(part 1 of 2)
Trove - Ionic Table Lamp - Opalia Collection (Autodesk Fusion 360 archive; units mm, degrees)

design "Marble Base - Ionic Table Lamp - Ketra Ready - 120V - Opalia Collection" references "Arca Tall", "Facet Petite", "Ketra - A20 Tunable Lamp", "Marble Base - Ionic Table Lamp - Ketra Ready - 120V", "Trove - TL", "Chinois", "Arca Petite"
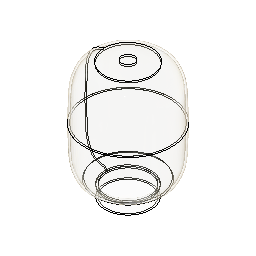
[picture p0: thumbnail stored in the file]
component_insert "Component Insert2"
component_insert "Component Insert3"
component_insert "Component Insert4"
component_insert "Component Insert5"
position "Position1"
component_insert "Component Insert6"
component_insert "Component Insert7"
component_insert "Component Insert8"

design "Arca Petite"
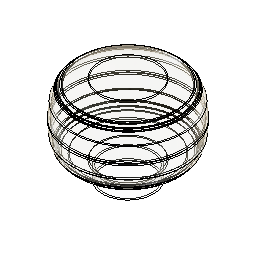
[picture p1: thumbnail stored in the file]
sketch "Sketch1" plane through (0, 0, 0) normal (0, 1, 0) x axis (1, 0, 0)
  line L1 (0, 101.6) -> (0, -101.6)
  line L2 (127, 0) -> (-127, 0)
  line L3 (63.5, 101.6) -> (-63.5, 101.6)
  perpendicular L1 L2
  parallel L2 L3
sketch "Sketch2" plane through (0, 0, 0) normal (0, 1, 0) x axis (1, 0, 0)
  line L1 (0, 101.6) -> (0, -101.6)
  line L2 (0, -76.2) -> (0, 101.6)
  line L3 (127, 0) -> (-127, 0)
  line L4 (114.3, 0) -> (-114.3, 0)
  line L5 (50.8, 101.6) -> (50.8, 63.5)
  line L6 (-50.8, 101.6) -> (50.8, 101.6)
  line L7 (-50.8, 63.5) -> (-50.8, 101.6)
  line L8 (63.5, 101.6) -> (-63.5, 101.6)
  line L9 (114.3, -76.2) -> (114.3, 63.5)
  line L10 (-114.3, -76.2) -> (114.3, -76.2)
  line L11 (-114.3, 63.5) -> (-114.3, -76.2)
  line L12 (-50.8, 63.5) -> (-114.3, 63.5)
  line L13 (114.3, 63.5) -> (50.8, 63.5)
  point P2 (0, 101.6)
  point P5 (0, 101.6)
  point P6 (0, -76.2)
  point P9 (-114.3, 0)
  point P10 (114.3, 0)
  point P11 (50.8, 101.6)
  point P19 (50.8, 63.5)
  coincident P2 P5
  coincident L1 P6
  coincident L3 P9
  coincident L3 P10
  vertical L5
  horizontal L6
  vertical L7
  coincident P11 L8
  horizontal L12
  vertical L9
  horizontal L10
  vertical L11
  coincident P19 L12
  collinear L12 L13
derived_base_feature "Derived Base Feature"
revolve "Revolve1" sketch "Sketch4" AlongAngle 360 bodies "Arca Petite"
shell "Shell1" innerThickness 3.81
component_from_bodies "Body->Comp"
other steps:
base_feature "Base Feature" bodies "Arca Petite"
create_component "CreateComponent1"
remove_body "RemoveBody1"
named bodies: "Arca Petite"

design "Neoprene Pad"
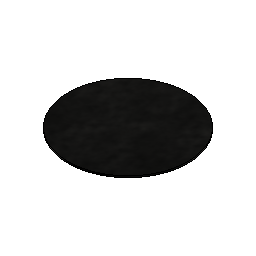
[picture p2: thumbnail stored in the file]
sketch "Sketch1" plane through (0, 0, 0) normal (0, 0, 1) x axis (1, 0, 0)
  circle C1 centre (0, 0) radius 57.15
  point P1 (0, 0)
  point P2 (0, 0)
  coincident P1 P2
extrude "Extrude1" new body sketch "Sketch1" along normal blind 1.5875 bodies "Neoprene Pad"
component_from_bodies "Body->Comp"
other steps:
base_feature "Base Feature" bodies "Neoprene Pad"
create_component "CreateComponent1"
remove_body "RemoveBody1"
named bodies: "Neoprene Pad"

design "T9 - Bulb"
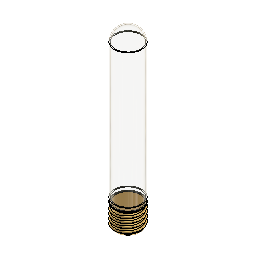
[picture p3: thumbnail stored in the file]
sketch "Sketch1" plane through (0, 0, 0) normal (0, 1, 0) x axis (1, 0, 0)
  line L1 (0, -166.37) -> (0, 0)
  line L2 (13.97, -13.97) -> (13.97, -152.4)
  line L3 (-13.97, -152.4) -> (-13.97, -13.97)
  line L4 (0, 0) -> (0, -166.37)
  line L5 (12.97, -13.97) -> (12.97, -152.4)
  line L6 (-12.97, -152.4) -> (-12.97, -13.97)
  line L7 (-12.3978, -10.16) -> (-13.4404, -10.16)
  line L8 (13.4404, -10.16) -> (12.3978, -10.16)
  arc A1 centre (0, -152.4) radius 13.97 clockwise from (13.97, -152.4) to (-13.97, -152.4)
  arc A2 centre (0, -152.4) radius 12.97 clockwise from (12.97, -152.4) to (-12.97, -152.4)
  arc A3 centre (0, -13.97) radius 13.97 clockwise from (13.4404, -10.16) to (13.97, -13.97)
  arc A4 centre (0, -13.97) radius 13.97 clockwise from (-13.97, -13.97) to (-13.4404, -10.16)
  arc A5 centre (0, -13.97) radius 12.97 clockwise from (12.3978, -10.16) to (12.97, -13.97)
  arc A6 centre (0, -13.97) radius 12.97 clockwise from (-12.97, -13.97) to (-12.3978, -10.16)
  point P1 (0, 0)
  point P2 (0, 0)
  point P3 (0, -166.37)
  point P10 (0, 0)
  point P17 (13.4404, -10.16)
  point P19 (12.3978, -10.16)
  point P4 (13.97, -152.4)
  point P5 (13.97, -13.97)
  coincident P1 P2
  vertical L1
  tangent L2 A3
  tangent L3 A3
  parallel L2 L3
  tangent L3 A1
  tangent L2 A1
  midpoint P3 A1
  coincident P1 P10
  perpendicular L1 L7
  coincident P17 L7
  concentric A3 A4
  coincident P10 A3
  concentric A1 A2
  tangent L5 A2
  tangent L5 A5
  tangent L6 A5
  tangent L6 A2
  coincident P19 L7
  concentric A5 A6
  collinear L7 L8
  dimension "d6" distance L2 L3 = 27.94
  dimension "d7" distance P4 P5 = 138.43
revolve "Revolve1" sketch "Sketch1" AlongAngle 360 bodies "T9"
derived_base_feature "Derived Base Feature" bodies "E26 Base"
align "Align1"
move "Move1"
component_from_bodies "Body->Comp1"
component_from_bodies "Body->Comp2"
copy_paste "CutPaste1"
copy_paste "CutPaste2"
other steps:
base_feature "Base Feature1" bodies "T9"
base_feature "Base Feature1" bodies "E26 Base"
create_component "CreateComponent1"
create_component "CreateComponent2"
remove_body "RemoveBody1"
create_component "CreateComponent3"
remove_body "RemoveBody2"
remove_instance "RemoveInstance1"
remove_instance "RemoveInstance2"
named bodies: "T9", "E26 Base"

design "Marble Base - Silicone Gasket"
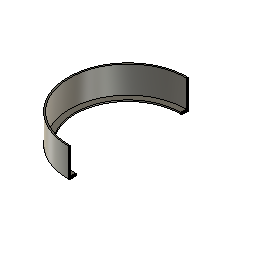
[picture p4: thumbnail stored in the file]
sketch "Sketch1" plane through (0, 0, 0) normal (0, 0, 1) x axis (1, 0, 0)
  circle C1 centre (0, 0) radius 53.34
  point P1 (0, 0)
  point P2 (0, 0)
  coincident P1 P2
extrude "Extrude1" new body sketch "Sketch1" along normal blind 25.4 bodies "Silicone Gasket"
shell "Shell1" innerThickness 1.27
sketch "Sketch2" plane through (0, 0, 1.27) normal (0, 0, 1) x axis (-1, 0, 0)
  circle C1 centre (0, 0) radius 52.07
  circle C2 centre (0, 0) radius 46.99
  concentric C1 C2
extrude "Extrude2" cut sketch "Sketch2" profile of C2 against normal blind 12.7
component_from_bodies "Body->Comp"
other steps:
base_feature "Base Feature" bodies "Silicone Gasket"
create_component "CreateComponent1"
remove_body "RemoveBody1"
named bodies: "Silicone Gasket"

design "2-Pole Plug End"
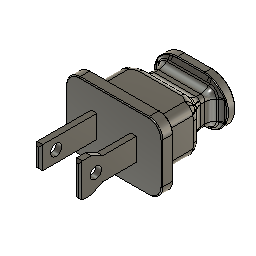
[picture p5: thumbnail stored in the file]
sketch "Sketch1" plane through (0, 0, 0) normal (0, 1, 0) x axis (1, 0, 0)
  line L1 (9.6837, 9.525) -> (-9.6837, 9.525)
  line L2 (13.4938, -5.715) -> (13.4938, 5.715)
  line L3 (-9.6837, -9.525) -> (9.6837, -9.525)
  line L4 (-13.4937, 5.715) -> (-13.4937, -5.715)
  line L5 (13.4938, -9.525) -> (-13.4937, 9.525)
  line L6 (-13.4937, -9.525) -> (13.4938, 9.525)
  arc A1 centre (-9.6837, -5.715) radius 3.81 clockwise from (-9.6837, -9.525) to (-13.4937, -5.715)
  arc A2 centre (9.6837, -5.715) radius 3.81 clockwise from (13.4938, -5.715) to (9.6837, -9.525)
  arc A3 centre (9.6837, 5.715) radius 3.81 clockwise from (9.6837, 9.525) to (13.4938, 5.715)
  arc A4 centre (-9.6837, 5.715) radius 3.81 clockwise from (-13.4937, 5.715) to (-9.6837, 9.525)
  point P6 (0, 0)
  point P1 (0, 0)
  point P5 (-13.4937, -9.525)
  point P4 (13.4938, -9.525)
  point P3 (13.4938, 9.525)
  point P2 (-13.4937, 9.525)
  horizontal L1
  perpendicular L1 L2
  parallel L1 L3
  parallel L2 L4
  coincident L5 P6
  coincident L6 P6
  coincident P1 P6
  coincident P5 L4
  coincident P5 L3
  tangent L4 A1
  tangent L3 A1
  coincident P4 L3
  coincident P4 L2
  tangent L3 A2
  tangent L2 A2
  equal A1 A2
  coincident P3 L2
  coincident P3 L1
  tangent L2 A3
  tangent L1 A3
  equal A1 A3
  coincident P2 L1
  coincident P2 L4
  tangent L1 A4
  tangent L4 A4
  equal A1 A4
  dimension "d1" distance P4 P5 = 26.9875
  dimension "d2" distance P2 P5 = 19.05
  dimension "d3" radius A1 = 3.81
extrude "Extrude1" new body sketch "Sketch1" profile of L1 L2 L3 L4 A1 A2 A3 A4 along normal blind 3.175
sketch "Sketch2" plane through (0, 3.175, 0) normal (0, 1, 0) x axis (-1, 0, 0)
  line L1 (9.6837, -9.525) -> (-9.6837, -9.525)
  line L2 (13.4937, 5.715) -> (13.4937, -5.715)
  line L3 (-9.6837, 9.525) -> (9.6837, 9.525)
  line L4 (-13.4938, -5.715) -> (-13.4938, 5.715)
  line L5 (10.16, -6.35) -> (-10.16, -6.35)
  line L6 (10.16, 6.35) -> (10.16, -6.35)
  line L7 (-10.16, 6.35) -> (10.16, 6.35)
  line L8 (-10.16, -6.35) -> (-10.16, 6.35)
  line L9 (10.16, 6.35) -> (-10.16, -6.35)
  line L10 (-10.16, 6.35) -> (10.16, -6.35)
  arc A1 centre (-9.6837, -5.715) radius 3.81 clockwise from (-9.6837, -9.525) to (-13.4938, -5.715)
  arc A2 centre (9.6837, -5.715) radius 3.81 clockwise from (13.4937, -5.715) to (9.6837, -9.525)
  arc A3 centre (9.6837, 5.715) radius 3.81 clockwise from (9.6837, 9.525) to (13.4937, 5.715)
  arc A4 centre (-9.6837, 5.715) radius 3.81 clockwise from (-13.4938, 5.715) to (-9.6837, 9.525)
  point P18 (0, 0)
  point P1 (0, 0)
  horizontal L5
  perpendicular L5 L6
  parallel L5 L7
  parallel L6 L8
  coincident L9 P18
  coincident L10 P18
  coincident P1 P18
extrude "Extrude2" add sketch "Sketch2" profile of L5 L6 L7 L8 along normal blind 9.525
sketch "Sketch3" plane through (0, 12.7, 0) normal (0, 1, 0) x axis (-1, 0, 0)
  line L1 (-10.16, -6.35) -> (-10.16, 6.35)
  line L2 (10.16, -6.35) -> (-10.16, -6.35)
  line L3 (10.16, 6.35) -> (10.16, -6.35)
  line L4 (-10.16, 6.35) -> (10.16, 6.35)
  line L5 (-7.1437, 3.9688) -> (7.1437, 3.9688)
  line L6 (-7.1437, -3.9688) -> (-7.1437, 3.9688)
  line L7 (7.1437, -3.9688) -> (-7.1437, -3.9688)
  line L8 (7.1437, 3.9688) -> (7.1437, -3.9688)
  line L9 (-7.1437, -3.9688) -> (7.1437, 3.9688)
  line L10 (7.1437, -3.9688) -> (-7.1437, 3.9688)
  point P10 (0, 0)
  point P1 (0, 0)
  point P8 (-7.1437, -3.9688)
  point P9 (7.1437, -3.9688)
  point P7 (-7.1437, 3.9688)
  horizontal L5
  perpendicular L5 L6
  parallel L5 L7
  parallel L6 L8
  coincident L9 P10
  coincident L10 P10
  coincident P1 P10
  dimension "d8" distance P8 P9 = 14.2875
  dimension "d9" distance P7 P8 = 7.9375
extrude "Extrude3" add sketch "Sketch3" profile of L5 L6 L7 L8 along normal blind 11.1125
fillet "Fillet1" radius 2.286 1.27 0.254
chamfer "Chamfer1" distance 3.429
fillet "Fillet2" radius 2.54 1.905
sketch "Sketch4" plane through (0, 23.8125, 0) normal (0, 1, 0) x axis (-1, 0, 0)
  line L1 (-7.1437, -2.6987) -> (-7.1437, 2.6987)
  line L2 (5.8737, -3.9688) -> (-5.8737, -3.9688)
  line L3 (7.1437, 2.6987) -> (7.1437, -2.6987)
  line L4 (-5.8737, 3.9688) -> (5.8737, 3.9688)
  line L5 (-3.81, 6.604) -> (3.81, 6.604)
  line L6 (3.81, -6.604) -> (-3.81, -6.604)
  line L7 (-10.414, 0) -> (10.414, 0)
  arc A1 centre (-5.8737, 2.6987) radius 1.27 clockwise from (-7.1437, 2.6987) to (-5.8737, 3.9688)
  arc A2 centre (-5.8737, -2.6987) radius 1.27 clockwise from (-5.8737, -3.9688) to (-7.1437, -2.6987)
  arc A3 centre (5.8737, -2.6987) radius 1.27 clockwise from (7.1437, -2.6987) to (5.8737, -3.9688)
  arc A4 centre (5.8737, 2.6987) radius 1.27 clockwise from (5.8737, 3.9688) to (7.1437, 2.6987)
  arc A5 centre (-3.81, 0) radius 6.604 clockwise from (-3.81, -6.604) to (-3.81, 6.604)
  arc A6 centre (3.81, 0) radius 6.604 clockwise from (3.81, 6.604) to (3.81, -6.604)
  point P20 (10.414, 0)
  point P21 (-10.414, 0)
  tangent L5 A5
  tangent A5 L6
  parallel L5 L6
  tangent L6 A6
  tangent L5 A6
  midpoint A6 P20
  midpoint A5 P21
  perpendicular L1 L7
extrude "Extrude4" add sketch "Sketch4" profile of A1 L1 A2 L2 A3 L3 A4 L4 L5 A5 L6 A6 against normal blind 2.286
chamfer "Chamfer2" distance 1.778
fillet "Fillet3" radius 1.778
fillet "Fillet4" radius 0.254
fillet "Fillet5" radius 0.254
fillet "Fillet6" radius 0.254
fillet "Fillet7" radius 3.175
sketch "Sketch5" plane through (0, 0, 0) normal (0, -1, 0) x axis (1, 0, 0)
  line L1 (-13.2397, -5.715) -> (-13.2397, 5.715)
  line L2 (9.6837, -9.271) -> (-9.6837, -9.271)
  line L3 (13.2397, 5.715) -> (13.2397, -5.715)
  line L4 (-9.6837, 9.271) -> (9.6837, 9.271)
  line L5 (-6.35, -3.175) -> (-6.35, 3.175)
  line L6 (6.35, 3.175) -> (-6.35, -3.175)
  line L7 (-6.35, 3.175) -> (6.35, -3.175)
  line L8 (-4.7625, 3.175) -> (-6.35, 3.175)
  line L9 (-4.7625, -3.175) -> (-4.7625, 3.175)
  line L10 (-6.35, -3.175) -> (-4.7625, -3.175)
  line L11 (-6.35, 3.175) -> (-6.35, -3.175)
  line L12 (0, -3.302) -> (0, 3.81)
  line L13 (4.7625, -3.175) -> (4.7625, 3.175)
  line L14 (4.7625, 3.175) -> (6.35, 3.175)
  line L15 (6.35, -3.175) -> (6.35, 3.175)
  line L16 (6.35, -3.175) -> (4.7625, -3.175)
  arc A1 centre (-9.6837, 5.715) radius 3.556 clockwise from (-13.2397, 5.715) to (-9.6837, 9.271)
  arc A2 centre (-9.6837, -5.715) radius 3.556 clockwise from (-9.6837, -9.271) to (-13.2397, -5.715)
  arc A3 centre (9.6837, -5.715) radius 3.556 clockwise from (13.2397, -5.715) to (9.6837, -9.271)
  arc A4 centre (9.6837, 5.715) radius 3.556 clockwise from (9.6837, 9.271) to (13.2397, 5.715)
  point P18 (0, 0)
  point P1 (0, 0)
  point P14 (-6.35, -3.175)
  point P27 (6.35, -3.175)
  point P17 (-6.35, 3.175)
  point P26 (6.35, 3.175)
  point P19 (-4.7625, 3.175)
  point P24 (4.7625, 3.175)
  point P20 (-4.7625, -3.175)
  point P25 (4.7625, -3.175)
  point P21 (-6.35, -3.175)
  point P28 (6.35, -3.175)
  point P15 (6.35, -3.175)
  point P16 (6.35, 3.175)
  coincident L6 P18
  coincident L7 P18
  coincident P1 P18
  horizontal L8
  vertical L9
  horizontal L10
  vertical L11
  vertical L12
  symmetric P14 L12 P27
  symmetric P17 L12 P26
  symmetric P19 L12 P24
  symmetric P20 L12 P25
  symmetric P21 L12 P28
  dimension "d36" distance P15 P16 = 6.35
  dimension "d37" distance P17 P19 = 1.5875
extrude "Extrude5" add sketch "Sketch5" profile of L5 L8 L9 L10 L11 L13 L14 L15 L16 along normal blind 15.875
sketch "Sketch7" plane through (0, 0, 3.175) normal (0, 0, 1) x axis (-1, 0, 0)
  line L1 (-4.7625, 0) -> (-6.35, 0)
  line L2 (-4.7625, 15.875) -> (-4.7625, 0)
  line L3 (-6.35, 15.875) -> (-4.7625, 15.875)
  line L4 (-6.35, 0) -> (-6.35, 15.875)
  line L5 (-4.7625, 15.875) -> (-6.35, 15.875)
  line L6 (-4.7625, 9.525) -> (-4.7625, 15.875)
  line L7 (-6.35, 9.525) -> (-4.7625, 9.525)
  line L8 (-6.35, 15.875) -> (-6.35, 9.525)
  point P5 (-6.35, 15.875)
  point P6 (-6.35, 15.875)
  point P9 (-6.35, 9.525)
  horizontal L5
  vertical L6
  horizontal L7
  vertical L8
  coincident P5 P6
  dimension "d45" distance P6 P9 = 6.35
extrude "Extrude7" add sketch "Sketch7" profile of L2 L3 L4 L5 L6 L7 L8 against normal blind 7.9375 and along normal blind 1.5875
chamfer "Chamfer3" distance 0.508
chamfer "Chamfer4" distance 0.635 distance 0.635
sketch "Sketch6" plane through (6.35, 0, 0) normal (1, 0, 0) x axis (0, 1, 0)
  line L1 (0, -3.175) -> (-9.525, -3.175)
  line L2 (0, 3.175) -> (0, -3.175)
  line L3 (-9.525, 3.175) -> (0, 3.175)
  line L4 (-15.367, -4.6355) -> (-15.367, 4.6355)
  line L5 (-11.43, 0) -> (-16.002, 0)
  line L6 (-9.525, -4.7625) -> (-15.24, -4.7625)
  line L7 (-9.525, -3.175) -> (-9.525, -4.7625)
  line L8 (-9.525, 4.7625) -> (-9.525, 3.175)
  line L9 (-15.24, 4.7625) -> (-9.525, 4.7625)
  line L10 (-15.24, -4.7625) -> (-15.367, -4.6355)
  line L11 (-15.367, 4.6355) -> (-15.24, 4.7625)
  circle C1 centre (-11.43, 0) radius 1.5875
  point P9 (-11.43, 0)
  point P10 (-11.43, 0)
  perpendicular L4 L5
  coincident P9 P10
  dimension "d42" diameter C1 = 3.175
extrude "Extrude6" cut sketch "Sketch6" profile of C1 against normal blind 20.32
chamfer "Chamfer5" distance 3.175 distance 1.5875 distance 3.175 distance 1.5875
component_from_bodies "Body->Comp"
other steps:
base_feature "Base Feature" bodies "2-Pole Plug End"
create_component "CreateComponent1"
remove_body "RemoveBody1"
named bodies: "2-Pole Plug End"

design "Facet Petite"
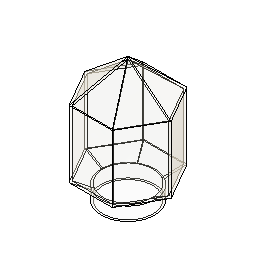
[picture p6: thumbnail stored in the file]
sketch "Sketch7" plane through (0, 0, 0) normal (1, 0, 0) x axis (0, 1, 0)
sketch "Sketch8" plane through (0, 0, 0) normal (0, 0, 1) x axis (1, 0, 0)
  circle C1 centre (0, 0) radius 50.8
  point P1 (0, 0)
  point P2 (0, 0)
  coincident P1 P2
  dimension "d17" diameter C1 = 101.6
extrude "Extrude5" new body sketch "Sketch8" along normal blind 25.4 and against normal blind 25.4
work_plane "WorkPlane1" AlongDistance 17.78
sketch "Sketch10" plane through (0, 0, 25.4) normal (0, 0, 1) x axis (-1, 0, 0)
  circle C1 centre (0, 0) radius 50.8
sketch "Sketch12" plane through (0, 0, 43.18) normal (0, 0, 1) x axis (1, 0, 0)
  line L1 (-82.1223, 0) -> (-41.0612, 71.12)
  line L2 (-41.0612, -71.12) -> (-82.1223, 0)
  line L3 (41.0612, -71.12) -> (-41.0612, -71.12)
  line L4 (82.1223, 0) -> (41.0612, -71.12)
  line L5 (41.0612, 71.12) -> (82.1223, 0)
  line L6 (-41.0612, 71.12) -> (41.0612, 71.12)
  point P1 (0, 0)
  point P8 (0, 0)
  coincident P1 P8
  dimension "d22" distance P8 L6 = 71.12
sketch "Sketch15" plane through (0, 0, 0) normal (0, 1, 0) x axis (1, 0, 0)
  line L1 (53.7365, -21.6801) -> (82.1223, -43.18)
  line L2 (-50.8, -25.4) -> (-82.1223, -43.18)
  point P2 (82.1223, -43.18)
  point P3 (82.1223, -43.18)
  point P5 (-82.1223, -43.18)
  point P7 (-82.1223, -43.18)
  point P6 (-50.8, -25.4)
  point P8 (-50.8, -25.4)
  coincident P2 P3
  coincident P5 P7
  coincident P6 P8
sketch "Sketch17" plane through (0, 0, 25.4) normal (0, 0, 1) x axis (-1, 0, 0)
  line L1 (51.3255, 0) -> (0, 0)
  line L2 (73.3235, 0) -> (0, 0)
  line L3 (-41.0612, -71.12) -> (-25.4, -43.9941)
  line L4 (-36.6617, -63.5) -> (-25.4, -43.9941)
  line L5 (78.4305, 0) -> (0, 0)
  line L6 (41.0612, -71.12) -> (25.4, -43.9941)
  line L7 (25.4, 43.9941) -> (41.0612, 71.12)
  line L8 (73.3235, 0) -> (0, 0)
  line L9 (-25.4, 43.9941) -> (-41.0612, 71.12)
  line L10 (0, 0) -> (0, 0)
  circle C1 centre (0, 0) radius 50.8
  point P1 (0, 0)
  point P4 (0, 0)
  point P2 (-41.0612, -71.12)
  point P6 (-41.0612, -71.12)
  point P3 (0, 0)
  point P7 (0, 0)
  point P9 (-25.4, -43.9941)
  point P12 (41.0612, -71.12)
  point P13 (41.0612, -71.12)
  point P15 (25.4, -43.9941)
  point P16 (41.0612, 71.12)
  point P17 (41.0612, 71.12)
  point P18 (25.4, 43.9941)
  point P19 (-41.0612, 71.12)
  point P20 (-41.0612, 71.12)
  point P21 (0, 0)
  point P23 (-25.4, 43.9941)
  point P25 (0, 0)
  point P24 (0, 0)
  point P26 (0, 0)
  horizontal L1
  coincident P1 P4
  coincident P2 P6
  horizontal L2
  coincident P3 P7
  coincident C1 P9
  coincident P12 P13
  horizontal L5
  coincident C1 P15
  coincident P16 P17
  coincident C1 P18
  coincident P19 P20
  horizontal L8
  coincident P1 P21
  coincident C1 P23
  coincident P1 P25
  coincident P24 P26
extrude "Extrude6" new body sketch "Sketch12" along normal blind 127
work_plane "WorkPlane2" AlongDistance 66.04
sketch "Sketch18" plane through (0, 0, 236.22) normal (0, 0, 1) x axis (1, 0, 0)
  line L1 (41.0612, -71.12) -> (0, 0)
  line L2 (82.1223, 0) -> (0, 0)
  line L3 (41.0612, 71.12) -> (0, 0)
  line L4 (-41.0612, 71.12) -> (0, 0)
  line L5 (-82.1223, 0) -> (0, 0)
  line L6 (-41.0612, -71.12) -> (0, 0)
  point P1 (0, 0)
  point P3 (0, 0)
  point P2 (41.0612, -71.12)
  point P4 (41.0612, -71.12)
  point P6 (0, 0)
  point P5 (82.1223, 0)
  point P7 (82.1223, 0)
  point P9 (0, 0)
  point P8 (41.0612, 71.12)
  point P10 (41.0612, 71.12)
  point P12 (0, 0)
  point P11 (-41.0612, 71.12)
  point P13 (-41.0612, 71.12)
  point P15 (0, 0)
  point P14 (-82.1223, 0)
  point P16 (-82.1223, 0)
  point P18 (0, 0)
  point P17 (-41.0612, -71.12)
  point P19 (-41.0612, -71.12)
  coincident P1 P3
  coincident P2 P4
  coincident P1 P6
  coincident P5 P7
  coincident P1 P9
  coincident P8 P10
  coincident P1 P12
  coincident P11 P13
  coincident P1 P15
  coincident P14 P16
  coincident P1 P18
  coincident P17 P19
loft "Loft1"
loft "Loft2" sketch "Sketch17"
component_from_bodies "Body->Comp"
extrude "Extrude1" cut of existing geometry blind -25.4
shell "Shell2" innerThickness 3.81
fillet "Fillet1" radius 7.62
fillet "Fillet2" radius 6.35
fillet "Fillet3" radius 6.35
fillet "Fillet4" radius 6.35
fillet "Fillet5" radius 6.35
fillet "Fillet6" radius 6.35
fillet "Fillet7" radius 3.81
fillet "Fillet8" radius 6.35
fillet "Fillet9" radius 6.35
fillet "Fillet10" radius 6.35
fillet "Fillet11" radius 6.35
fillet "Fillet12" radius 6.35
fillet "Fillet13" radius 2.286
shell "Shell1" innerThickness 2.54
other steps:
base_feature "Base Feature"
create_component "CreateComponent3"
remove_body "RemoveBody2"

design "Chinois"
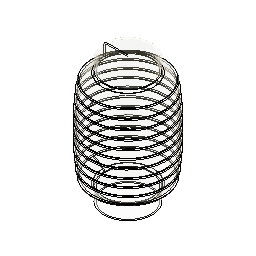
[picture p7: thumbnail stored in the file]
named bodies: "Chinois"

design "Marble Base - Plastic Insert"
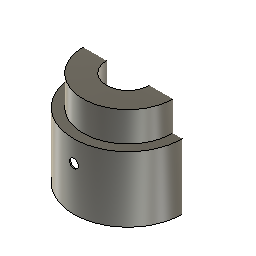
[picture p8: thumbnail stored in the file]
sketch "Sketch1" plane through (0, 0, 0) normal (0, 0, 1) x axis (1, 0, 0)
  circle C1 centre (0, 0) radius 50.038
  point P1 (0, 0)
  point P2 (0, 0)
  coincident P1 P2
  dimension "d1" diameter C1 = 100.076
extrude "Extrude1" new body sketch "Sketch1" along normal blind 72.898 bodies "Plastic Insert"
shell "Shell1" innerThickness 1.016
work_plane "WorkPlane1" AlongDistance 18.034
sketch "Sketch2" plane through (0, 0, 90.932) normal (0, 0, 1) x axis (1, 0, 0)
  circle C1 centre (0, 0) radius 20.701
  point P1 (0, 0)
  point P2 (0, 0)
  coincident P1 P2
  dimension "d6" diameter C1 = 41.402
extrude "Extrude2" add sketch "Sketch2" against normal blind 65.024
shell "Shell2" innerThickness 1.016
sketch "Sketch3" plane through (0, 0, 0) normal (0, 1, 0) x axis (1, 0, 0)
  line L1 (5.08, -20.32) -> (-5.08, -20.32)
  line L2 (5.08, 20.32) -> (5.08, -20.32)
  line L3 (-5.08, 20.32) -> (5.08, 20.32)
  line L4 (-5.08, -20.32) -> (-5.08, 20.32)
  line L5 (5.08, 20.32) -> (-5.08, -20.32)
  line L6 (-5.08, 20.32) -> (5.08, -20.32)
  point P6 (0, 0)
  point P1 (0, 0)
  horizontal L1
  perpendicular L1 L2
  parallel L1 L3
  parallel L2 L4
  coincident L5 P6
  coincident L6 P6
  coincident P1 P6
extrude "Extrude3" cut sketch "Sketch3" profile of L1 L2 L3 L4 along normal blind 91.44
sketch "Sketch4" plane through (0, 0, 0) normal (0, 1, 0) x axis (1, 0, 0)
  line L1 (0, -40.64) -> (0, 0)
  circle C1 centre (0, -40.64) radius 4.064
  point P1 (0, 0)
  point P2 (0, 0)
  point P3 (0, -40.64)
  point P4 (0, -40.64)
  coincident P1 P2
  vertical L1
  coincident P3 P4
  dimension "d12" diameter C1 = 8.128
work_plane "WorkPlane2" AlongDistance -91.44
sketch "Sketch5" plane through (0, -91.44, 0) normal (0, 1, 0) x axis (1, 0, 0)
  circle C1 centre (0, -40.64) radius 4.064
extrude "Extrude4" cut sketch "Sketch5" along normal blind 63.5
sketch "Sketch6" plane through (0, 0, 26.924) normal (0, 0, 1) x axis (-1, 0, 0)
  circle C1 centre (0, 0) radius 19.685
  circle C2 centre (0, 0) radius 5.461
  concentric C1 C2
  dimension "d16" diameter C2 = 10.922
extrude "Extrude5" cut sketch "Sketch6" profile of C2 against normal blind 15.24
sketch "Sketch7" plane through (0, 0, 72.898) normal (0, 0, 1) x axis (-1, 0, 0)
  circle C1 centre (0, 0) radius 20.701
  circle C2 centre (0, 0) radius 50.038
  circle C3 centre (0, 0) radius 20.701
  circle C4 centre (0, 0) radius 45.72
  point P1 (0, 0)
  point P3 (0, 0)
  point P4 (0, 0)
  coincident P1 P3
  coincident P1 P4
extrude "Extrude6" add sketch "Sketch7" profile of C1 C3 C4 along normal blind 18.034
sketch "Sketch8" plane through (0, 0, 71.882) normal (0, 0, -1) x axis (1, 0, 0)
  circle C1 centre (0, 0) radius 20.701
  circle C2 centre (0, 0) radius 49.022
  circle C3 centre (0, 0) radius 20.701
  circle C4 centre (0, 0) radius 44.704
  point P1 (0, 0)
  point P3 (0, 0)
  point P4 (0, 0)
  coincident P1 P3
  coincident P1 P4
  dimension "d21" diameter C4 = 89.408
extrude "Extrude7" cut sketch "Sketch8" profile of C1 C3 C4 against normal blind 17.78
extrude "Extrude8" add of existing geometry blind 9.398
extrude "Extrude9" cut of existing geometry blind -9.398
component_from_bodies "Body->Comp"
offset_faces "OffsetFaces1" distance 4.445
offset_faces "OffsetFaces2" distance -4.445
offset_faces "OffsetFaces3" distance 3.175
offset_faces "OffsetFaces4" distance 3.175
offset_faces "OffsetFaces5" distance 3.175
offset_faces "OffsetFaces6" distance -3.175
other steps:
base_feature "Base Feature" bodies "Plastic Insert"
create_component "CreateComponent1"
remove_body "RemoveBody1"
named bodies: "Plastic Insert"

design "Arca Tall"
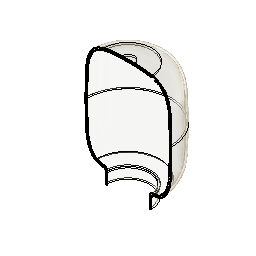
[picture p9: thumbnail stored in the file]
derived_base_feature "Derived Base Feature" bodies "Balon"
work_plane "WorkPlane1" AlongDistance 0
sketch "Sketch1" plane through (0, 0, 0) normal (0, 1, 0) x axis (1, 0, 0)
  line L1 (0, 317.5) -> (0, 2.9083)
  curve K1 (-82.9821, 124.2212) -> (-50.8, 237.8015)
  curve K2 (-51.0925, 237.681) -> (-50.8, 237.8015)
  curve K3 (-51.3855, 237.5558) -> (-51.0925, 237.681)
  curve K4 (-54.7608, 236.0513) -> (-51.3855, 237.5558)
  curve K5 (-57.9615, 234.05) -> (-54.7608, 236.0513)
  curve K6 (-67.2727, 226.749) -> (-57.9615, 234.05)
  curve K7 (-69.0552, 224.2615) -> (-67.2727, 226.749)
  curve K8 (-72.1872, 218.7832) -> (-69.0552, 224.2615)
  curve K9 (-74.1213, 215.1556) -> (-72.1872, 218.7832)
  curve K10 (-78.3031, 204.3965) -> (-74.1213, 215.1556)
  curve K11 (-79.7275, 197.3397) -> (-78.3031, 204.3965)
  curve K12 (-81.3333, 185.4664) -> (-79.7275, 197.3397)
  curve K13 (-81.6254, 178.4008) -> (-81.3333, 185.4664)
  curve K14 (-82.49, 152.2133) -> (-81.6254, 178.4008)
  curve K15 (-82.9821, 136.067) -> (-82.49, 152.2133)
  curve K16 (-82.9821, 124.2212) -> (-82.9821, 136.067)
  curve K17 (50.8, 237.7999) -> (82.9821, 124.2212)
  curve K18 (82.9821, 140.3031) -> (82.9821, 124.2212)
  curve K19 (81.9353, 169.4257) -> (82.9821, 140.3031)
  curve K20 (81.3621, 183.6489) -> (81.9353, 169.4257)
  curve K21 (80.9478, 189.8724) -> (81.3621, 183.6489)
  curve K22 (77.8147, 206.9858) -> (80.9478, 189.8724)
  curve K23 (74.9652, 213.2153) -> (77.8147, 206.9858)
  curve K24 (69.4688, 224.1531) -> (74.9652, 213.2153)
  curve K25 (67.2512, 226.458) -> (69.4688, 224.1531)
  curve K26 (61.5696, 231.3138) -> (67.2512, 226.458)
  curve K27 (57.377, 234.6711) -> (61.5696, 231.3138)
  curve K28 (52.0556, 237.2628) -> (57.377, 234.6711)
  curve K29 (51.4313, 237.5413) -> (52.0556, 237.2628)
  curve K30 (50.8, 237.7999) -> (51.4313, 237.5413)
  line L2 (-50.8, 317.5) -> (-50.8, 237.8015)
  line L3 (50.8, 317.5) -> (50.8, 237.7999)
  line L4 (-19.0713, 6.7501) -> (-19.0713, 6.7501)
  curve K31 (82.9821, 124.1958) -> (40.1509, 7.3012)
  curve K32 (41.8198, 7.6176) -> (40.1509, 7.3012)
  curve K33 (43.2113, 8.0663) -> (41.8198, 7.6176)
  curve K34 (47.0139, 9.2854) -> (43.2113, 8.0663)
  curve K35 (47.3314, 9.3805) -> (47.0139, 9.2854)
  curve K36 (50.1192, 10.3272) -> (47.3314, 9.3805)
  curve K37 (51.833, 11.0085) -> (50.1192, 10.3272)
  curve K38 (57.8313, 14.1895) -> (51.833, 11.0085)
  curve K39 (61.4491, 17.0488) -> (57.8313, 14.1895)
  curve K40 (66.8203, 21.5867) -> (61.4491, 17.0488)
  curve K41 (68.5372, 23.5528) -> (66.8203, 21.5867)
  curve K42 (71.2201, 27.8971) -> (68.5372, 23.5528)
  curve K43 (74.7424, 33.8984) -> (71.2201, 27.8971)
  curve K44 (78.2342, 44.8406) -> (74.7424, 33.8984)
  curve K45 (79.6792, 50.3463) -> (78.2342, 44.8406)
  curve K46 (81.3558, 63.5576) -> (79.6792, 50.3463)
  curve K47 (81.6386, 70.4415) -> (81.3558, 63.5576)
  curve K48 (82.4897, 96.2198) -> (81.6386, 70.4415)
  curve K49 (82.9814, 112.3523) -> (82.4897, 96.2198)
  curve K50 (82.9821, 124.1958) -> (82.9814, 112.3523)
  curve K51 (-40.1501, 7.301) -> (-82.9821, 124.1958)
  curve K52 (-82.9813, 110.5256) -> (-82.9821, 124.1958)
  curve K53 (-82.2545, 88.8594) -> (-82.9813, 110.5256)
  curve K54 (-81.6277, 70.519) -> (-82.2545, 88.8594)
  curve K55 (-81.3572, 64.3441) -> (-81.6277, 70.519)
  curve K56 (-79.4149, 46.8924) -> (-81.3572, 64.3441)
  curve K57 (-76.5204, 38.9768) -> (-79.4149, 46.8924)
  curve K58 (-73.5142, 32.2947) -> (-76.5204, 38.9768)
  curve K59 (-72.5556, 30.3818) -> (-73.5142, 32.2947)
  curve K60 (-69.7914, 25.3691) -> (-72.5556, 30.3818)
  curve K61 (-68.3824, 23.4028) -> (-69.7914, 25.3691)
  curve K62 (-64.5419, 19.5456) -> (-68.3824, 23.4028)
  curve K63 (-62.3002, 17.7646) -> (-64.5419, 19.5456)
  curve K64 (-53.6583, 11.1976) -> (-62.3002, 17.7646)
  curve K65 (-49.6968, 10.1396) -> (-53.6583, 11.1976)
  curve K66 (-43.4141, 8.1331) -> (-49.6968, 10.1396)
  curve K67 (-41.9704, 7.6516) -> (-43.4141, 8.1331)
  curve K68 (-40.1963, 7.3098) -> (-41.9704, 7.6516)
  curve K69 (-40.1732, 7.3054) -> (-40.1963, 7.3098)
  curve K70 (-40.1501, 7.301) -> (-40.1732, 7.3054)
  line L5 (-82.9821, 124.1958) -> (-82.9821, 124.2212)
  line L6 (82.9821, 124.2212) -> (82.9821, 124.1958)
  line L7 (0, 317.5) -> (-50.8, 317.5)
  line L8 (7.2015, 3.048) -> (0, 3.048)
  line L9 (0, 3.048) -> (-7.2015, 3.048)
  arc A1 centre (0, 188.595) radius 185.6867 clockwise from (-7.2015, 3.048) to (-40.1502, 7.301)
  arc A2 centre (0, 188.595) radius 185.6867 clockwise from (40.151, 7.3012) to (7.2015, 3.048)
  point P38 (-40.1502, 7.301)
  point P43 (40.1509, 7.3012)
  point P62 (-40.1501, 7.301)
  point P81 (40.151, 7.3012)
  point P84 (0, 3.048)
  vertical L1
  horizontal L4
  coincident P38 K51
  symmetric L1 A1 A2
  coincident A2 P43
  coincident A1 P62
  coincident K31 P81
  perpendicular L2 L7
  horizontal L8
  coincident L1 P84
  horizontal L9
revolve "Revolve1" sketch "Sketch1" AlongAngle 360
shell "Shell1" innerThickness 3.81
fillet "Fillet1" radius 6.35 bodies "Balon v3"
offset_faces "OffsetFaces1" distance -50.8
move "Move1"
move "Move2"
component_from_bodies "Body->Comp1"
component_from_bodies "Body->Comp2"
sketch "Sketch2" plane through (0, 0, 0) normal (0, 1, 0) x axis (1, 0, 0)
  line L1 (-85.5221, 124.2212) -> (-85.5221, 124.1961)
  curve K1 (-58.9057, 236.4383) -> (-50.8, 241.7989)
  curve K2 (-50.8, 241.554) -> (-50.8, 241.7989)
  curve K3 (-50.904, 240.933) -> (-50.8, 241.554)
  curve K4 (-51.2936, 240.2837) -> (-50.904, 240.933)
  curve K5 (-51.734, 239.7561) -> (-51.2936, 240.2837)
  curve K6 (-53.328, 238.5038) -> (-51.734, 239.7561)
  curve K7 (-54.0892, 238.1997) -> (-53.328, 238.5038)
  curve K8 (-58.9057, 236.4383) -> (-54.0892, 238.1997)
  curve K9 (-89.3309, 124.2212) -> (-58.9057, 236.4383)
  curve K10 (-62.6336, 234.9735) -> (-58.9057, 236.4383)
  curve K11 (-65.581, 233.1032) -> (-62.6336, 234.9735)
  curve K12 (-73.0224, 227.0019) -> (-65.581, 233.1032)
  curve K13 (-74.8981, 224.836) -> (-73.0224, 227.0019)
  curve K14 (-78.1104, 219.6097) -> (-74.8981, 224.836)
  curve K15 (-80.2663, 215.561) -> (-78.1104, 219.6097)
  curve K16 (-84.0943, 205.8277) -> (-80.2663, 215.561)
  curve K17 (-85.4655, 200.1154) -> (-84.0943, 205.8277)
  curve K18 (-87.4092, 188.5789) -> (-85.4655, 200.1154)
  curve K19 (-87.7349, 182.3889) -> (-87.4092, 188.5789)
  curve K20 (-88.4233, 165.9645) -> (-87.7349, 182.3889)
  curve K21 (-89.328, 138.6964) -> (-88.4233, 165.9645)
  curve K22 (-89.3309, 124.2212) -> (-89.328, 138.6964)
  line L2 (-89.3309, 124.1958) -> (-89.3309, 124.2212)
  curve K23 (-46.5001, 7.301) -> (-89.3309, 124.1958)
  curve K24 (-89.3314, 112.4293) -> (-89.3309, 124.1958)
  curve K25 (-88.8181, 95.3068) -> (-89.3314, 112.4293)
  curve K26 (-88.346, 81.2892) -> (-88.8181, 95.3068)
  curve K27 (-88.0298, 70.4902) -> (-88.346, 81.2892)
  curve K28 (-87.1514, 58.328) -> (-88.0298, 70.4902)
  curve K29 (-86.3326, 50.6119) -> (-87.1514, 58.328)
  curve K30 (-81.0932, 33.6688) -> (-86.3326, 50.6119)
  curve K31 (-77.3163, 27.4309) -> (-81.0932, 33.6688)
  curve K32 (-74.8955, 23.6666) -> (-77.3163, 27.4309)
  curve K33 (-73.5108, 22.0741) -> (-74.8955, 23.6666)
  curve K34 (-70.2346, 19.0457) -> (-73.5108, 22.0741)
  curve K35 (-64.8094, 14.3548) -> (-70.2346, 19.0457)
  curve K36 (-56.6696, 10.3041) -> (-64.8094, 14.3548)
  curve K37 (-54.0053, 9.483) -> (-56.6696, 10.3041)
  curve K38 (-49.1487, 7.9411) -> (-54.0053, 9.483)
  curve K39 (-48.3482, 7.6526) -> (-49.1487, 7.9411)
  curve K40 (-46.5001, 7.301) -> (-48.3482, 7.6526)
  line L3 (0, 266.7) -> (0, 0)
  line L4 (0, 3.048) -> (-7.7894, 3.048)
  line L5 (-50.8, 266.7) -> (-50.8, 241.7989)
  line L6 (0, 266.7) -> (-50.8, 266.7)
  arc A1 centre (-6.9779, 188.7329) radius 185.6867 clockwise from (-7.7894, 3.048) to (-46.5001, 7.301)
  point P1 (0, 0)
  point P44 (0, 0)
  point P46 (0, 3.048)
  point P5 (-50.8, 241.554)
  point P49 (0, 266.7)
  coincident P1 P44
  coincident L3 P46
  coincident P5 L5
  coincident L3 P49
revolve "Revolve2" sketch "Sketch2" AlongAngle 360 bodies "Balon v3"
shell "Shell2" innerThickness 3.81
component_from_bodies "Body->Comp3"
remove_instance "RemoveInstance1"
remove_instance "RemoveInstance2"
sketch "Sketch1" plane through (0, 0, 0) normal (0, 1, 0) x axis (1, 0, 0)
  line L1 (-6.35, 3.048) -> (-14.1394, 3.048)
  curve K1 (-52.8501, 7.301) -> (-95.6809, 124.1958)
  curve K2 (-95.6814, 112.4293) -> (-95.6809, 124.1958)
  curve K3 (-95.1681, 95.3068) -> (-95.6814, 112.4293)
  curve K4 (-94.696, 81.2892) -> (-95.1681, 95.3068)
  curve K5 (-94.3798, 70.4902) -> (-94.696, 81.2892)
  curve K6 (-93.5014, 58.328) -> (-94.3798, 70.4902)
  curve K7 (-92.6826, 50.6119) -> (-93.5014, 58.328)
  curve K8 (-87.4432, 33.6688) -> (-92.6826, 50.6119)
  curve K9 (-83.6663, 27.4309) -> (-87.4432, 33.6688)
  curve K10 (-81.2455, 23.6666) -> (-83.6663, 27.4309)
  curve K11 (-79.8608, 22.0741) -> (-81.2455, 23.6666)
  curve K12 (-76.5846, 19.0457) -> (-79.8608, 22.0741)
  curve K13 (-71.12, 13.97) -> (-76.5846, 19.0457)
  curve K14 (-62.23, 10.16) -> (-71.12, 13.97)
  curve K15 (-60.3553, 9.483) -> (-62.23, 10.16)
  curve K16 (-55.4987, 7.9411) -> (-60.3553, 9.483)
  curve K17 (-54.6982, 7.6526) -> (-55.4987, 7.9411)
  curve K18 (-52.8501, 7.301) -> (-54.6982, 7.6526)
  line L2 (-95.6809, 124.1958) -> (-95.6809, 124.2212)
  line L3 (0, 266.7) -> (0, 0)
  line L4 (0, 3.048) -> (-6.35, 3.048)
  line L5 (-95.6809, 124.2466) -> (-95.6809, 124.2212)
  line L6 (-50.8, 266.7) -> (-50.8, 241.7989)
  line L7 (0, 266.7) -> (-50.8, 266.7)
  curve K19 (-71.6837, 232.5587) -> (-50.8, 241.7989)
  curve K20 (-50.8, 237.8015) -> (-50.8, 241.7989)
  curve K21 (-53.6019, 236.5654) -> (-50.8, 237.8015)
  curve K22 (-59.7861, 236.0598) -> (-53.6019, 236.5654)
  curve K23 (-64.4375, 235.2772) -> (-59.7861, 236.0598)
  curve K24 (-69.8917, 233.4707) -> (-64.4375, 235.2772)
  curve K25 (-71.6837, 232.5587) -> (-69.8917, 233.4707)
  curve K26 (-71.6837, 232.5587) -> (-95.6809, 124.2466)
  curve K27 (-95.6814, 136.0132) -> (-95.6809, 124.2466)
  curve K28 (-95.1681, 153.1357) -> (-95.6814, 136.0132)
  curve K29 (-94.696, 167.1533) -> (-95.1681, 153.1357)
  curve K30 (-94.3798, 177.9523) -> (-94.696, 167.1533)
  curve K31 (-93.5014, 190.1145) -> (-94.3798, 177.9523)
  curve K32 (-92.6826, 197.8306) -> (-93.5014, 190.1145)
  curve K33 (-87.4432, 214.7737) -> (-92.6826, 197.8306)
  curve K34 (-83.6663, 221.0115) -> (-87.4432, 214.7737)
  curve K35 (-81.2455, 224.7759) -> (-83.6663, 221.0115)
  curve K36 (-79.8608, 226.3684) -> (-81.2455, 224.7759)
  curve K37 (-77.083, 228.9361) -> (-79.8608, 226.3684)
  curve K38 (-75.5537, 230.2778) -> (-77.083, 228.9361)
  curve K39 (-71.6837, 232.5587) -> (-75.5537, 230.2778)
  curve K40 (-50.8, 244.8458) -> (-50.8, 244.8469)
  curve K41 (-50.8, 244.8465) -> (-50.8, 244.8469)
  curve K42 (-50.8, 244.8462) -> (-50.8, 244.8465)
  curve K43 (-50.8, 244.8458) -> (-50.8, 244.8462)
  arc A1 centre (-13.3279, 188.7329) radius 185.6867 clockwise from (-14.1394, 3.048) to (-52.8501, 7.301)
  point P26 (0, 3.048)
  point P33 (-50.8, 237.8015)
  point P35 (-50.8, 237.8015)
  point P40 (-71.6837, 232.5587)
  point P53 (-50.8, 244.8458)
  coincident L3 P26
  perpendicular L3 L4
  coincident P33 P35
  coincident K19 P40
  coincident L6 P53
sketch "Sketch2" plane through (0, 0, 0) normal (0, 1, 0) x axis (1, 0, 0)
  line L1 (-95.6809, 124.1958) -> (-95.6809, 124.2212)
  line L2 (0, 266.7) -> (-50.8, 266.7)
  curve K1 (-58.9317, 239.3909) -> (-50.8, 244.8469)
  curve K2 (-50.8, 244.602) -> (-50.8, 244.8469)
  curve K3 (-50.904, 243.981) -> (-50.8, 244.602)
  curve K4 (-51.2936, 243.3317) -> (-50.904, 243.981)
  curve K5 (-51.734, 242.8041) -> (-51.2936, 243.3317)
  curve K6 (-53.328, 241.5518) -> (-51.734, 242.8041)
  curve K7 (-54.0892, 241.2477) -> (-53.328, 241.5518)
  curve K8 (-58.9317, 239.3909) -> (-54.0892, 241.2477)
  line L3 (-50.8, 266.7) -> (-50.8, 244.8458)
  curve K9 (-52.8501, 7.301) -> (-95.6809, 124.1958)
  curve K10 (-95.6814, 112.4293) -> (-95.6809, 124.1958)
  curve K11 (-95.1681, 95.3068) -> (-95.6814, 112.4293)
  curve K12 (-94.696, 81.2892) -> (-95.1681, 95.3068)
  curve K13 (-94.3798, 70.4902) -> (-94.696, 81.2892)
  curve K14 (-93.5014, 58.328) -> (-94.3798, 70.4902)
  curve K15 (-92.6826, 50.6119) -> (-93.5014, 58.328)
  curve K16 (-87.4432, 33.6688) -> (-92.6826, 50.6119)
  curve K17 (-83.6663, 27.4309) -> (-87.4432, 33.6688)
  curve K18 (-81.2455, 23.6666) -> (-83.6663, 27.4309)
  curve K19 (-79.8608, 22.0741) -> (-81.2455, 23.6666)
  curve K20 (-76.5846, 19.0457) -> (-79.8608, 22.0741)
  curve K21 (-73.7599, 16.6033) -> (-76.5846, 19.0457)
  curve K22 (-65.532, 11.7145) -> (-73.7599, 16.6033)
  curve K23 (-60.3553, 9.483) -> (-65.532, 11.7145)
  curve K24 (-55.4987, 7.9411) -> (-60.3553, 9.483)
  curve K25 (-54.6982, 7.6526) -> (-55.4987, 7.9411)
  curve K26 (-52.8501, 7.301) -> (-54.6982, 7.6526)
  line L4 (-95.6809, 124.2466) -> (-95.6809, 124.2212)
  line L5 (0, 3.048) -> (-6.35, 3.048)
  line L6 (-6.35, 3.048) -> (-14.1394, 3.048)
  curve K27 (-58.9317, 239.3909) -> (-95.6809, 124.2466)
  curve K28 (-95.6814, 136.0132) -> (-95.6809, 124.2466)
  curve K29 (-95.1681, 153.1357) -> (-95.6814, 136.0132)
  curve K30 (-94.696, 167.1533) -> (-95.1681, 153.1357)
  curve K31 (-94.3798, 177.9523) -> (-94.696, 167.1533)
  curve K32 (-93.5014, 190.1145) -> (-94.3798, 177.9523)
  curve K33 (-92.6826, 197.8306) -> (-93.5014, 190.1145)
  curve K34 (-87.4432, 214.7737) -> (-92.6826, 197.8306)
  curve K35 (-83.6663, 221.0115) -> (-87.4432, 214.7737)
  curve K36 (-81.2455, 224.7759) -> (-83.6663, 221.0115)
  curve K37 (-79.8608, 226.3684) -> (-81.2455, 224.7759)
  curve K38 (-76.5846, 229.3968) -> (-79.8608, 226.3684)
  curve K39 (-73.7599, 231.8391) -> (-76.5846, 229.3968)
  curve K40 (-65.833, 236.5491) -> (-73.7599, 231.8391)
  curve K41 (-61.4585, 238.4785) -> (-65.833, 236.5491)
  curve K42 (-58.9317, 239.3909) -> (-61.4585, 238.4785)
  line L7 (0, 3.048) -> (0, 266.7)
  arc A1 centre (-13.3279, 188.7329) radius 185.6867 clockwise from (-14.1394, 3.048) to (-52.8501, 7.301)
  point P52 (-50.8, 244.8458)
  coincident K1 P52
  perpendicular L5 L7
revolve "Revolve1" sketch "Sketch1" AlongAngle 360 bodies "Balon v3.3"
shell "Shell1" innerThickness 3.81
revolve "Revolve2" sketch "Sketch2" AlongAngle 360 bodies "Balon v3.2"
shell "Shell2" innerThickness 3.81
component_from_bodies "Body->Comp1"
component_from_bodies "Body->Comp2"
position "Position1"
remove_instance "RemoveInstance1" bodies "Balon v3"
remove_instance "RemoveInstance2"
move "Move1"
position "Position2" bodies "Balon v3"
sketch "Sketch3" plane through (0, 0, 0) normal (0, 1, 0) x axis (1, 0, 0)
  line L1 (0, 50.8) -> (0, -304.8)
  line L2 (127, 50.8) -> (127, -304.8)
  line L3 (-127, 50.8) -> (-127, -304.8)
  line L4 (139.7, 25.4) -> (-139.7, 25.4)
  line L5 (139.7, -292.1) -> (-139.7, -292.1)
  line L6 (95.25, 50.8) -> (95.25, -304.8)
  vertical L1
  dimension "d6" = 127
  dimension "d12" = -127
  dimension "d17" distance L4 L5 = 317.5
  dimension "d18" = 95.25
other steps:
base_feature "Base Feature1" bodies "Balon v3.3"
base_feature "Base Feature1" bodies "Balon v3.2"
base_feature "Base Feature1" bodies "Balon"
base_feature "Base Feature1" bodies "Balon v3"
base_feature "Base Feature1" bodies "Balon v2"
create_component "CreateComponent1"
remove_body "RemoveBody1"
create_component "CreateComponent2"
remove_body "RemoveBody2"
create_component "CreateComponent3"
remove_body "RemoveBody3" bodies "Balon v3"
create_component "CreateComponent1"
create_component "CreateComponent2"
remove_body "RemoveBody1" bodies "Balon v3"
create_component "CreateComponent3"
remove_body "RemoveBody2" bodies "Balon v3"
named bodies: "Balon", "Balon v2", "Balon v3", "Balon v3.3", "Balon v3.2"

design "Marble Base - Ionic Table Lamp - Ketra Ready - 120V" references "Marble Base - Ionic Table Lamp - 120V"
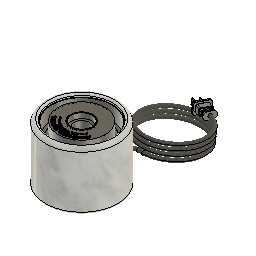
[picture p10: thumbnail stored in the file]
external_derived "ExternalDerived1" bodies "Coiled - SVT (Blk Fabric)", "Body1", "Marble Base", "Body2", "Silicone Gasket", "Plastic Insert"
derived_instance "DerivedInstance1"
derived_instance "DerivedInstance2"
derived_instance "DerivedInstance3"
derived_instance "DerivedInstance4"
derived_instance "DerivedInstance5"
derived_instance "DerivedInstance6"
derived_instance "DerivedInstance7"
derived_instance "DerivedInstance8"
derived_instance "DerivedInstance9"
derived_instance "DerivedInstance10"
derived_instance "DerivedInstance11"
derived_instance "DerivedInstance12"
offset_faces "OffsetFaces1" distance 3.81
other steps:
derived_base_feature "Derived Base Feature1" bodies "Rubber Grommet"
derived_base_feature "Derived Base Feature1" bodies "Neoprene Pad"
derived_base_feature "Derived Base Feature1" bodies "2-Pole Plug End"
derived_base_feature "Derived Base Feature1" bodies "Body1"
derived_base_feature "Derived Base Feature1" bodies "Body1", "Body2"
derived_base_feature "Derived Base Feature1" bodies "Body1"
derived_base_feature "Derived Base Feature1" bodies "Silicone Gasket"
derived_base_feature "Derived Base Feature1" bodies "Plastic Insert"
derived_base_feature "Derived Base Feature1" bodies "Body1"
derived_base_feature "Derived Base Feature1" bodies "Body1"
derived_base_feature "Derived Base Feature1" bodies "Coiled - SVT (Blk Fabric)"
derived_base_feature "Derived Base Feature1" bodies "Marble Base"
create_component "CreateComponent1"
create_component "CreateComponent2"
create_component "CreateComponent3"
create_component "CreateComponent4"
create_component "CreateComponent5"
create_component "CreateComponent6"
create_component "CreateComponent7"
create_component "CreateComponent8"
create_component "CreateComponent9"
create_component "CreateComponent10"
create_component "CreateComponent11"
create_component "CreateComponent12"
named bodies: "Coiled - SVT (Blk Fabric)", "Marble Base", "Body1", "Body2", "Plastic Insert", "Silicone Gasket", "Neoprene Pad", "2-Pole Plug End", "Rubber Grommet"

design "Rubber Grommet"
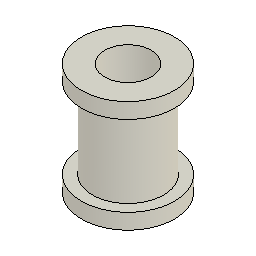
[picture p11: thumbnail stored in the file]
sketch "Sketch1" plane through (0, 0, 0) normal (0, 1, 0) x axis (1, 0, 0)
  line L1 (0, 3.048) -> (0, -12.7)
  line L2 (5.842, 0.508) -> (5.842, -12.7)
  line L3 (3.81, 3.048) -> (3.81, -15.24)
  line L4 (7.62, -12.7) -> (7.62, -15.24)
  line L5 (7.62, 3.048) -> (7.62, 0.508)
  line L6 (7.62, 0.508) -> (5.842, 0.508)
  line L7 (7.62, -12.7) -> (5.842, -12.7)
  line L8 (7.62, -15.24) -> (3.81, -15.24)
  line L9 (7.62, 3.048) -> (3.81, 3.048)
  vertical L1
  collinear L4 L5
revolve "Revolve1" sketch "Sketch1" AlongAngle 360 bodies "Rubber Grommet"
component_from_bodies "Body->Comp"
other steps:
base_feature "Base Feature" bodies "Rubber Grommet"
create_component "CreateComponent1"
remove_body "RemoveBody1"
named bodies: "Rubber Grommet"

design "Marble Base - Ionic Table Lamp - 120V" references "T9 - Bulb", "Arca Tall", "Facet Petite", "T9-5In", "Marble Base - Plastic Insert", "Rubber Grommet", "Neoprene Pad", "2-Pole Plug End", "Trove - TL", "Balon v2", "Chinois", "Marble Base - Silicone Gasket"
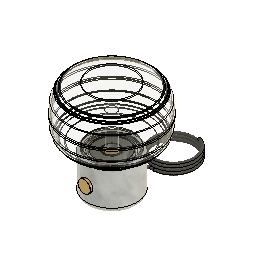
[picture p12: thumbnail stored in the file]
sketch "Sketch1" plane through (0, 0, 0) normal (0, 0, 1) x axis (1, 0, 0)
  circle C1 centre (0, 0) radius 63.5
  point P1 (0, 0)
  point P2 (0, 0)
  coincident P1 P2
extrude "Extrude1" new body sketch "Sketch1" along normal blind 101.6 bodies "Marble Base"
sketch "Sketch2" plane through (0, 0, 101.6) normal (0, 0, 1) x axis (-1, 0, 0)
  circle C1 centre (0, 0) radius 63.5
  circle C2 centre (0, 0) radius 53.975
  concentric C1 C2
  dimension "d3" diameter C2 = 107.95
extrude "Extrude2" cut sketch "Sketch2" profile of C2 against normal blind 34.925
sketch "Sketch3" plane through (0, 0, 66.675) normal (0, 0, 1) x axis (-1, 0, 0)
  circle C1 centre (0, 0) radius 53.975
  circle C2 centre (0, 0) radius 49.276
  point P1 (0, 0)
  point P3 (0, 0)
  coincident P1 P3
  dimension "d6" diameter C2 = 98.552
extrude "Extrude3" cut sketch "Sketch3" profile of C2 against normal blind 45.72
sketch "Sketch4" plane through (0, 0, 0) normal (0, 1, 0) x axis (1, 0, 0)
  circle C1 centre (0, -50.8) radius 3.81
  dimension "d9" diameter C1 = 7.62
extrude "Extrude4" cut sketch "Sketch4" against normal blind 127
sketch "Sketch5" plane through (0, 0, 0) normal (0, 1, 0) x axis (1, 0, 0)
  line L1 (0, -25.4) -> (0, 0)
  line L2 (0, -30.48) -> (0, -25.4)
  circle C1 centre (0, -30.48) radius 5.08
  point P1 (0, 0)
  point P2 (0, 0)
  point P4 (0, -30.48)
  point P5 (0, -30.48)
  coincident P1 P2
  vertical L1
  parallel L1 L2
  coincident P4 P5
  dimension "d12" diameter C1 = 10.16
extrude "Extrude5" cut sketch "Sketch5" profile of C1 along normal blind 114.3
fillet "Fillet1" radius 6.35 3.175 4.064
derived_base_feature "Derived Base Feature1" bodies "Rotary Switch"
derived_base_feature "Derived Base Feature1" bodies "Coiled - SVT (Blk Fabric)"
derived_base_feature "Derived Base Feature1" bodies "Glass Globe"
derived_base_feature "Derived Base Feature1" bodies "Metal Housing"
derived_base_feature "Derived Base Feature1" bodies "Metal Socket Cover"
derived_base_feature "Derived Base Feature1" bodies "Porcelain Socket"
derived_base_feature "Derived Base Feature1" bodies "Brass Dial - Dimmer Knob"
component_from_bodies "Body->Comp1"
offset_faces "OffsetFaces1" distance 12.7
offset_faces "OffsetFaces2" distance -12.7
derived_base_feature "Derived Base Feature1" bodies "Solitaire Petite"
move "Move1"
offset_faces "OffsetFaces1" distance 20.32
move "Move2"
extrude "Extrude6" add of existing geometry blind 25.4
offset_faces "OffsetFaces2" distance -3.81
fillet "Fillet2" radius 2.54
move "Move3"
derived_base_feature "Derived Base Feature2" bodies "Facet Petite"
move "Move4"
offset_faces "OffsetFaces1" distance 2.54
move "Move1"
derived_base_feature "Derived Base Feature1" bodies "Body1"
derived_base_feature "Derived Base Feature1" bodies "Body1"
derived_base_feature "Derived Base Feature1" bodies "Body1"
derived_base_feature "Derived Base Feature1" bodies "Body1"
derived_base_feature "Derived Base Feature1" bodies "Body1"
derived_base_feature "Derived Base Feature1" bodies "Body1", "Body2"
derived_base_feature "Derived Base Feature1" bodies "Body1"
position "Position1"
external_derived "ExternalDerived5" bodies "Plastic Insert"
derived_instance "DerivedInstance15"
offset_faces "OffsetFaces1" distance 3.81
offset_faces "OffsetFaces2" distance -1.0414
move "Move6"
external_derived "ExternalDerived6" sketch "Sketch3" bodies "Silicone Gasket"
derived_instance "DerivedInstance16"
offset_faces "OffsetFaces3" distance -10.795
move "Move1"
move_face "MoveFace1"
position "Position2"
position "Position3"
position "Position4"
position "Position5"
move "Move2"
position "Position6"
offset_faces "OffsetFaces2" distance -7.62
chamfer "Chamfer1" distance 0.381
remove_instance "RemoveInstance1"
remove_instance "RemoveInstance2"
remove_instance "RemoveInstance3"
remove_instance "RemoveInstance4"
move "Move1"
derived_base_feature "Derived Base Feature5" bodies "Oculo Petite"
align "Align1"
external_derived "ExternalDerived8"
derived_base_feature "Derived Base Feature7" bodies "Balon v2"
derived_base_feature "Derived Base Feature8" bodies "Balon v3"
align "Align3"
align "Align4"
external_derived "ExternalDerived10"
component_insert "Component Insert1"
position "Position7"
position "Position8"
derived_base_feature "Derived Base Feature11" bodies "Trove - TL"
move "Move10"
move "Move11"
remove_instance "RemoveInstance5"
split "Split1" bodies "Trove - TL (1)"
remove_body "RemoveBody2"
remove_body "RemoveBody3"
external_derived "ExternalDerived13" bodies "Trove - TL"
derived_instance "DerivedInstance20"
remove_body "RemoveBody4"
remove_body "RemoveBody5"
component_insert "Component Insert2"
component_insert "Component Insert3"
component_from_bodies "Body->Comp2"
remove_body "RemoveBody7"
move "Move12"
move "Move13"
sketch "Sketch6" plane through (0, 0, 97.917) normal (0, 0, 1) x axis (-1, 0, 0)
  circle C1 centre (0, 0) radius 41.275
  circle C2 centre (0, 0) radius 19.685
  arc A1 centre (0, 0) radius 29.3982 clockwise from (-27.6283, 10.0466) to (27.6283, 10.0466)
  arc A2 centre (0, 0) radius 26.2232 clockwise from (-24.6444, 8.9616) to (24.6444, 8.9616)
  arc A3 centre (0, 0) radius 32.5732 clockwise from (-30.6121, 11.1317) to (30.6121, 11.1317)
  arc A4 centre (0, 0) radius 35.7482 clockwise from (-33.596, 12.2167) to (33.596, 12.2167)
  point P1 (0, 0)
  point P3 (0, 0)
  coincident P1 P3
  dimension "d37" = -3.175
  dimension "d38" = 3.175
  dimension "d39" = 6.35
  dimension "d40" Text1-Height = 2.54
  dimension "d41" Text2-Height = 2.54
  dimension "d42" Text3-Height = 2.54
  dimension "d43" Text4-Height = 2.54
extrude "Extrude1" cut sketch "Sketch6" against normal blind 0.254
external_derived "ExternalDerived14" bodies "Rubber Grommet"
derived_instance "DerivedInstance19"
external_derived "ExternalDerived15" bodies "2-Pole Plug End"
derived_instance "DerivedInstance18"
external_derived "ExternalDerived16" bodies "Neoprene Pad"
derived_instance "DerivedInstance17"
position "Position9"
position "Position10"
position "Position11"
position "Position12"
external_derived "ExternalDerived17" bodies "Chinois"
derived_instance "DerivedInstance21"
position "Position13"
move "Move3"
remove_body "RemoveBody8"
component_insert "Component Insert4"
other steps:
derived_base_feature "Derived Base Feature1" bodies "Trove - TL"
derived_base_feature "Derived Base Feature1" bodies "Chinois"
derived_base_feature "Derived Base Feature1" bodies "Rubber Grommet"
derived_base_feature "Derived Base Feature1" bodies "2-Pole Plug End"
derived_base_feature "Derived Base Feature1" bodies "Neoprene Pad"
move "Move1"
base_feature "Base Feature1" bodies "Oculo Petite"
derived_base_feature "Derived Base Feature1" bodies "Plastic Insert"
derived_base_feature "Derived Base Feature1" bodies "Silicone Gasket"
base_feature "Base Feature1" bodies "Marble Base"
move "Move8"
derived_base_feature "Derived Base Feature"
create_component "CreateComponent1"
create_component "CreateComponent2"
create_component "CreateComponent3"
